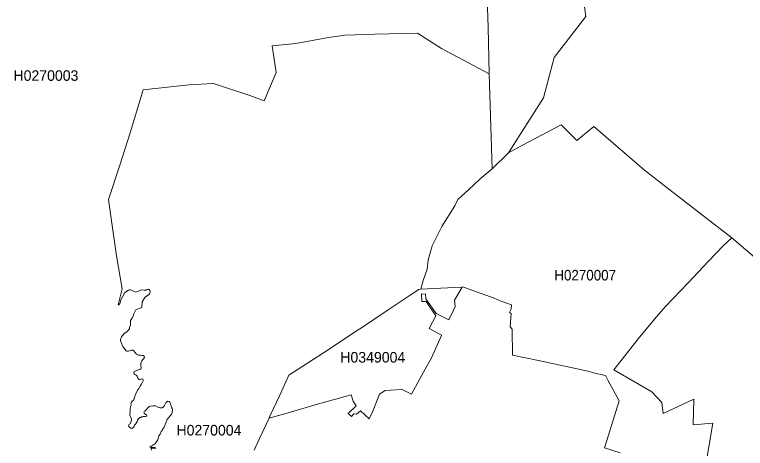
# Model space of a CAD drawing. Extents: x 369010 to 739155, y 6377141 to 6616555.
# Drawn here: x 407141 to 414085, y 6458637 to 6462758 of the extents above; entities that cross this region are included whole.
import ezdxf
from ezdxf.enums import TextEntityAlignment as Align

# ---------------------------------------------------------------- set-up
doc = ezdxf.new("R2010")
doc.units = 0
doc.header["$LTSCALE"] = 40
doc.layers.add('1', color=7, linetype='Continuous', lineweight=13)
doc.layers.add('2', color=7, linetype='Continuous')

msp = doc.modelspace()

# ---------------------------------------------------------------- linework, layer by layer
at = {"layer": '1'}
for points in [[(408412.9, 6460148.03), (408400.82, 6460147.7), (408391.72, 6460141.08), (408371.86, 6460141.08), (408355.8, 6460143.73), (408336.6, 6460138.59), (408302.84, 6460124.69), (408293.74, 6460122.54), (408275.86, 6460128.5), (408242.1, 6460142.4), (408233, 6460142.4), (408224.23, 6460139.75), (408187.49, 6460116.42), (408145.45, 6460036.98), (408145.78, 6460026.22), (408142.3, 6460013.14), (408132.54, 6460000.07), (408125.59, 6460001.56), (408162.33, 6460152.5), (408109.04, 6460466.62), (408067.16, 6460755.43), (408032.9, 6461001.7), (408141.31, 6461329.4), (408240.28, 6461636.41), (408362.09, 6462043.38), (408797.7, 6462090.05), (409029.9, 6462102.63), (409376.3, 6461990.09), (409513.34, 6461940.11), (409627.54, 6462207.89), (409587.48, 6462463.1), (409814.39, 6462482.79), (410124.54, 6462539.89), (410282.93, 6462563.06), (410562.8, 6462573.82), (410968.45, 6462580.61), (411198.83, 6462437.78), (411650.33, 6462196.8), (411641.39, 6462640.19), (411620.04, 6463290.95)], [(411620.04, 6463290.95), (411641.39, 6462640.19), (411650.33, 6462196.8), (411665.55, 6461694.99), (411678.79, 6461293.32), (411834.2, 6461446.57), (412167.53, 6461966.92), (412267.16, 6462351.38), (412568.05, 6462739.66), (412547.19, 6462906.48)], [(412547.19, 6462906.48), (412568.05, 6462739.66), (412267.16, 6462351.38), (412167.53, 6461966.92), (411834.2, 6461446.57), (411965.78, 6461518.73), (412333.19, 6461711.21), (412483.31, 6461561.93), (412644.18, 6461694), (413125.3, 6461280.41), (413369.75, 6461089.42), (413957.12, 6460637.26), (414215.97, 6460415.81)], [(409417.35, 6458619.6), (409468.98, 6458729.82), (409559.35, 6458924.79), (409567.46, 6458942), (409660.47, 6459141.1), (409748.02, 6459331.1), (409879.93, 6459418.16), (410075.55, 6459543.28), (410406.56, 6459763.4), (410436.85, 6459783.42), (410690.24, 6459951.91), (410890.83, 6460084.81), (410981.19, 6460145.21), (411001.05, 6460149.52), (411024.06, 6460231.11), (411060.3, 6460339.52), (411071.72, 6460427.07), (411109.79, 6460562.62), (411201.15, 6460744.67), (411324.78, 6460942.45), (411351.43, 6461003.19), (411454.2, 6461094.21), (411564.59, 6461197.65), (411678.79, 6461293.32), (411665.55, 6461694.99), (411650.33, 6462196.8), (411198.83, 6462437.78), (410968.45, 6462580.61), (410562.8, 6462573.82), (410282.93, 6462563.06), (410124.54, 6462539.89), (409814.39, 6462482.79), (409587.48, 6462463.1), (409627.54, 6462207.89), (409513.34, 6461940.11), (409376.3, 6461990.09), (409029.9, 6462102.63), (408797.7, 6462090.05), (408362.09, 6462043.38), (408240.28, 6461636.41), (408141.31, 6461329.4), (408032.9, 6461001.7), (408067.16, 6460755.43), (408109.04, 6460466.62), (408162.33, 6460152.5), (408125.59, 6460001.56), (408132.54, 6460000.07), (408142.3, 6460013.14), (408145.78, 6460026.22), (408145.45, 6460036.98), (408187.49, 6460116.42), (408224.23, 6460139.75), (408233, 6460142.4), (408242.1, 6460142.4), (408275.86, 6460128.5), (408293.74, 6460122.54), (408302.84, 6460124.69), (408336.6, 6460138.59), (408355.8, 6460143.73), (408371.86, 6460141.08), (408391.72, 6460141.08), (408400.82, 6460147.7), (408412.9, 6460148.03), (408426.14, 6460140.75), (408427.96, 6460123.2), (408421.34, 6460101.03), (408382.78, 6460073.72), (408354.31, 6460028.37), (408350.18, 6459975.57), (408292.58, 6459953.06), (408271.73, 6459909.7), (408270.24, 6459904.08), (408258.98, 6459872.63), (408247.4, 6459861.21), (408242.27, 6459851.28), (408240.78, 6459808.91), (408231.67, 6459786.57), (408231.84, 6459771.51), (408206.68, 6459744.7), (408181.86, 6459729.8), (408158.03, 6459697.69), (408146.27, 6459671.71), (408146.27, 6459658.47), (408158.19, 6459636.46), (408159.18, 6459627.85)], [(413701.25, 6458426.62), (413774.57, 6458875.63), (413589.7, 6458861.9), (413595.16, 6459103.7), (413302.72, 6458969.64), (413289.97, 6459072.42), (413196.13, 6459172.55), (412834.34, 6459382.24), (413077.8, 6459692.89), (413241.81, 6459887.86), (413323.9, 6459980.7), (413541.71, 6460208.77), (413735.18, 6460417.14), (413876.52, 6460564.27), (413957.12, 6460637.26), (413369.75, 6461089.42), (413125.3, 6461280.41), (412644.18, 6461694), (412483.31, 6461561.93), (412333.19, 6461711.21), (411965.78, 6461518.73), (411834.2, 6461446.57), (411678.79, 6461293.32), (411564.59, 6461197.65), (411454.2, 6461094.21), (411351.43, 6461003.19), (411324.78, 6460942.45), (411201.15, 6460744.67), (411109.79, 6460562.62), (411071.72, 6460427.07), (411060.3, 6460339.52), (411024.06, 6460231.11), (411001.05, 6460149.52), (411189.73, 6460160.61), (411392.97, 6460170.04), (411401.74, 6460170.37), (411484.66, 6460139.59), (411617.22, 6460093.08), (411697.66, 6460063.62), (411755.42, 6460040.12), (411861.84, 6460000.07), (411860.02, 6459958.53), (411843.97, 6459926.75), (411860.02, 6459917.15), (411850.92, 6459791.04), (411868.46, 6459770.84), (411872.6, 6459523.58), (412120.52, 6459470.46), (412603.46, 6459367.18), (412640.04, 6459354.44), (412755.06, 6459328.78), (412778.07, 6459285.75), (412884.99, 6459089.63), (412752.25, 6458660.97), (412745.63, 6458642.6), (412896.9, 6458593.95)], [(414215.97, 6460415.81), (413957.12, 6460637.26), (413876.52, 6460564.27), (413735.18, 6460417.14), (413541.71, 6460208.77), (413323.9, 6459980.7), (413241.81, 6459887.86), (413077.8, 6459692.89), (412834.34, 6459382.24), (413196.13, 6459172.55), (413289.97, 6459072.42), (413302.72, 6458969.64), (413595.16, 6459103.7), (413589.7, 6458861.9), (413774.57, 6458875.63), (413701.25, 6458426.62)], [(408270.9, 6458837.07), (408265.77, 6458830.45), (408260.47, 6458827.47), (408253.19, 6458825.98), (408244.25, 6458829.62), (408231.67, 6458837.73), (408226.54, 6458843.69), (408224.39, 6458851.14), (408225.05, 6458858.42), (408231.01, 6458865.87), (408237.63, 6458871), (408241.27, 6458875.47), (408248.72, 6458896.82), (408250.87, 6458905.59), (408250.21, 6458913.7), (408245.08, 6458928.76), (408236.14, 6458949.45), (408234.65, 6458961.2), (408239.12, 6458988.51), (408239.78, 6459015.82), (408242.27, 6459031.87), (408245.74, 6459038.16), (408247.23, 6459046.93), (408246.57, 6459059.51), (408248.06, 6459069.11), (408251.7, 6459076.56), (408258.32, 6459083.84), (408268.58, 6459092.77), (408272.39, 6459097.91), (408279.01, 6459118.59), (408296.72, 6459165.27), (408312.11, 6459194.06), (408320.22, 6459205.81), (408332.8, 6459229.32), (408342.4, 6459245.2), (408357.13, 6459266.55), (408362.42, 6459277.64), (408362.42, 6459287.9), (408360.93, 6459295.35), (408354.31, 6459298.17), (408350.51, 6459298.17), (408332.14, 6459288.57), (408324.69, 6459292.37), (408316.58, 6459299.65), (408308.47, 6459310.08), (408306.98, 6459315.87), (408304, 6459322.49), (408295.89, 6459332.09), (408283.48, 6459338.71), (408278.18, 6459344.67), (408275.37, 6459351.29), (408274.54, 6459359.4), (408278.18, 6459368.17), (408299.7, 6459378.1), (408332.14, 6459387.04), (408340.91, 6459392.83), (408344.71, 6459399.45), (408344.71, 6459407.56), (408341.74, 6459421.63), (408339.42, 6459437.85), (408339.42, 6459446.62), (408349.84, 6459468.8), (408363.25, 6459484.85), (408373.68, 6459501.07), (408373.18, 6459512), (408365.4, 6459519.11), (408348.85, 6459519.78), (408336.94, 6459523.42), (408318.9, 6459522.59), (408300.03, 6459530.37), (408267.26, 6459568.93), (408248.39, 6459571.25), (408222.74, 6459560.32), (408207.68, 6459559.33), (408199.57, 6459562.48), (408178.05, 6459593.09), (408168.29, 6459603.35), (408159.18, 6459627.85), (408158.19, 6459636.46), (408146.27, 6459658.47), (408146.27, 6459671.71), (408158.03, 6459697.69), (408181.86, 6459729.8), (408206.68, 6459744.7), (408231.84, 6459771.51), (408231.67, 6459786.57), (408240.78, 6459808.91), (408242.27, 6459851.28), (408247.4, 6459861.21), (408258.98, 6459872.63), (408270.24, 6459904.08), (408271.73, 6459909.7), (408292.58, 6459953.06), (408350.18, 6459975.57), (408354.31, 6460028.37), (408382.78, 6460073.72), (408421.34, 6460101.03), (408427.96, 6460123.2), (408426.14, 6460140.75), (408412.9, 6460148.03)], [(411392.97, 6460170.04), (411321.47, 6460044.59), (411328.59, 6459986.33), (411308.89, 6459944.13), (411268.51, 6459859.39), (411148.19, 6459918.97), (411049.21, 6460059.15), (411045.9, 6460103.01), (411007.51, 6460105), (411009.83, 6460032.18), (411051.2, 6460032.01), (411143.39, 6459894.64), (411079.5, 6459775.98), (411198.33, 6459712.09), (411197.34, 6459709.77), (411103, 6459497.43), (411025.22, 6459361.88), (410911.85, 6459153.18), (410824.13, 6459196.21), (410660.78, 6459185.79), (410609.8, 6459152.19), (410579.18, 6459077.55), (410542.44, 6458984.87), (410508.84, 6458918.83), (410427.25, 6458994.47), (410389.52, 6458961.86), (410363.86, 6458965.67), (410341.52, 6458940.84), (410310.9, 6458966.66), (410386.54, 6459040.14), (410358.24, 6459084.67), (410339.53, 6459146.73), (409997.6, 6459050.9), (409707.47, 6458966.16), (409568.12, 6458927.11), (409559.35, 6458924.79), (409468.98, 6458729.82), (409417.35, 6458619.6)], [(412896.9, 6458593.95), (412745.63, 6458642.6), (412752.25, 6458660.97), (412884.99, 6459089.63), (412778.07, 6459285.75), (412755.06, 6459328.78), (412640.04, 6459354.44), (412603.46, 6459367.18), (412120.52, 6459470.46), (411872.6, 6459523.58), (411868.46, 6459770.84), (411850.92, 6459791.04), (411860.02, 6459917.15), (411843.97, 6459926.75), (411860.02, 6459958.53), (411861.84, 6460000.07), (411755.42, 6460040.12), (411697.66, 6460063.62), (411617.22, 6460093.08), (411484.66, 6460139.59), (411401.74, 6460170.37), (411392.97, 6460170.04)], [(408159.18, 6459627.85), (408168.29, 6459603.35), (408178.05, 6459593.09), (408199.57, 6459562.48), (408207.68, 6459559.33), (408222.74, 6459560.32), (408248.39, 6459571.25), (408267.26, 6459568.93), (408300.03, 6459530.37), (408318.9, 6459522.59), (408336.94, 6459523.42), (408348.85, 6459519.78), (408365.4, 6459519.11), (408373.18, 6459512), (408373.68, 6459501.07), (408363.25, 6459484.85), (408349.84, 6459468.8), (408339.42, 6459446.62), (408339.42, 6459437.85), (408341.74, 6459421.63), (408344.71, 6459407.56), (408344.71, 6459399.45), (408340.91, 6459392.83), (408332.14, 6459387.04), (408299.7, 6459378.1), (408278.18, 6459368.17), (408274.54, 6459359.4), (408275.37, 6459351.29), (408278.18, 6459344.67), (408283.48, 6459338.71), (408295.89, 6459332.09), (408304, 6459322.49), (408306.98, 6459315.87), (408308.47, 6459310.08), (408316.58, 6459299.65), (408324.69, 6459292.37), (408332.14, 6459288.57), (408350.51, 6459298.17), (408354.31, 6459298.17), (408360.93, 6459295.35)], [(408360.93, 6459295.35), (408362.42, 6459287.9), (408362.42, 6459277.64), (408357.13, 6459266.55), (408342.4, 6459245.2), (408332.8, 6459229.32), (408320.22, 6459205.81), (408312.11, 6459194.06), (408296.72, 6459165.27), (408279.01, 6459118.59), (408272.39, 6459097.91), (408268.58, 6459092.77), (408258.32, 6459083.84), (408251.7, 6459076.56), (408248.06, 6459069.11), (408246.57, 6459059.51), (408247.23, 6459046.93), (408245.74, 6459038.16), (408242.27, 6459031.87), (408239.78, 6459015.82), (408239.12, 6458988.51), (408234.65, 6458961.2), (408236.14, 6458949.45), (408245.08, 6458928.76), (408250.21, 6458913.7), (408250.87, 6458905.59), (408248.72, 6458896.82), (408241.27, 6458875.47), (408237.63, 6458871), (408231.01, 6458865.87), (408225.05, 6458858.42), (408224.39, 6458851.14), (408226.54, 6458843.69), (408231.67, 6458837.73), (408244.25, 6458829.62), (408253.19, 6458825.98), (408260.47, 6458827.47), (408265.77, 6458830.45), (408270.9, 6458837.07), (408276.03, 6458846.67), (408279.67, 6458856.27), (408288.61, 6458868.02), (408295.23, 6458875.47), (408305.49, 6458890.86), (408309.3, 6458905.59), (408315.92, 6458914.53), (408330.65, 6458929.26), (408340.91, 6458931.41), (408346.2, 6458935.05), (408354.98, 6458935.88), (408363.91, 6458939.52), (408373.51, 6458941.01), (408379.3, 6458940.35), (408385.92, 6458936.54), (408392.54, 6458939.52), (408397.01, 6458943.99), (408397.01, 6458947.63), (408393.37, 6458955.08), (408378.64, 6458964.67), (408373.51, 6458970.47), (408370.53, 6458975.6), (408369.04, 6458981.56), (408373.51, 6458987.51), (408378.64, 6458991.82), (408385.92, 6458996.29), (408394.03, 6459005.89), (408402.97, 6459018.46), (408412.57, 6459029.55), (408418.53, 6459033.86), (408430.28, 6459037.5), (408453.95, 6459040.48), (408466.36, 6459039.81), (408480.43, 6459040.48), (408501.78, 6459027.24), (408509.89, 6459023.59), (408524.29, 6459021.44), (408532.4, 6459021.44), (408542.66, 6459022.77), (408550.1, 6459025.08), (408556.06, 6459030.88), (408564.17, 6459043.45), (408577.41, 6459068.61), (408586.35, 6459079.53), (408595.12, 6459086.15), (408609.19, 6459083.34), (408616.47, 6459074.4), (408622.43, 6459064.14), (408628.39, 6459037.5), (408632.03, 6459026.57), (408637.16, 6459015.48), (408640.8, 6459005.22), (408640.47, 6458999.6), (408639.31, 6458978.58), (408630.54, 6458962.85), (408591.98, 6458909.89), (408584.03, 6458895.66), (408561.36, 6458838.89), (408556.39, 6458829.95), (408550.44, 6458824.49), (408548.45, 6458816.05)], [(408482.08, 6458636.48), (408480.43, 6458639.96), (408473.15, 6458644.26), (408436.57, 6458646.41), (408427.47, 6458646.91), (408428.46, 6458649.89), (408434.91, 6458655.68), (408473.97, 6458678.52), (408489.7, 6458698.21), (408501.12, 6458717.58), (408506.58, 6458733.3), (408507.57, 6458747.37), (408511.54, 6458754.82), (408523.79, 6458770.21), (408534.71, 6458795.86), (408540.67, 6458803.31), (408548.45, 6458816.05), (408550.44, 6458824.49), (408556.39, 6458829.95), (408561.36, 6458838.89), (408584.03, 6458895.66), (408591.98, 6458909.89), (408630.54, 6458962.85), (408639.31, 6458978.58), (408640.47, 6458999.6), (408640.8, 6459005.22), (408637.16, 6459015.48), (408632.03, 6459026.57), (408628.39, 6459037.5), (408622.43, 6459064.14), (408616.47, 6459074.4), (408609.19, 6459083.34), (408595.12, 6459086.15), (408586.35, 6459079.53), (408577.41, 6459068.61), (408564.17, 6459043.45), (408556.06, 6459030.88), (408550.1, 6459025.08), (408542.66, 6459022.77), (408532.4, 6459021.44), (408524.29, 6459021.44), (408509.89, 6459023.59), (408501.78, 6459027.24), (408480.43, 6459040.48), (408466.36, 6459039.81), (408453.95, 6459040.48), (408430.28, 6459037.5), (408418.53, 6459033.86), (408412.57, 6459029.55), (408402.97, 6459018.46), (408394.03, 6459005.89), (408385.92, 6458996.29), (408378.64, 6458991.82), (408373.51, 6458987.51), (408369.04, 6458981.56), (408370.53, 6458975.6), (408373.51, 6458970.47), (408378.64, 6458964.67), (408393.37, 6458955.08), (408397.01, 6458947.63), (408397.01, 6458943.99), (408392.54, 6458939.52), (408385.92, 6458936.54), (408379.3, 6458940.35), (408373.51, 6458941.01), (408363.91, 6458939.52), (408354.98, 6458935.88), (408346.2, 6458935.05), (408340.91, 6458931.41), (408330.65, 6458929.26), (408315.92, 6458914.53), (408309.3, 6458905.59), (408305.49, 6458890.86), (408295.23, 6458875.47), (408288.61, 6458868.02), (408279.67, 6458856.27), (408276.03, 6458846.67), (408270.9, 6458837.07)], [(408548.45, 6458816.05), (408540.67, 6458803.31), (408534.71, 6458795.86), (408523.79, 6458770.21), (408511.54, 6458754.82), (408507.57, 6458747.37), (408506.58, 6458733.3), (408501.12, 6458717.58), (408489.7, 6458698.21), (408473.97, 6458678.52), (408434.91, 6458655.68), (408428.46, 6458649.89), (408427.47, 6458646.91), (408436.57, 6458646.41), (408473.15, 6458644.26), (408480.43, 6458639.96), (408482.08, 6458636.48)], [(408471.82, 6458634.33), (408461.39, 6458639.79), (408438.06, 6458638.96), (408441.7, 6458620.43)], [(408441.7, 6458620.43), (408438.06, 6458638.96), (408461.39, 6458639.79), (408471.82, 6458634.33)]]:
    msp.add_lwpolyline(points, dxfattribs=at)
msp.add_lwpolyline([(411392.97, 6460170.04), (411189.73, 6460160.61), (411001.05, 6460149.52), (410981.19, 6460145.21), (410890.83, 6460084.81), (410690.24, 6459951.91), (410436.85, 6459783.42), (410406.56, 6459763.4), (410075.55, 6459543.28), (409879.93, 6459418.16), (409748.02, 6459331.1), (409660.47, 6459141.1), (409567.46, 6458942), (409559.35, 6458924.79), (409568.12, 6458927.11), (409707.47, 6458966.16), (409997.6, 6459050.9), (410339.53, 6459146.73), (410358.24, 6459084.67), (410386.54, 6459040.14), (410310.9, 6458966.66), (410341.52, 6458940.84), (410363.86, 6458965.67), (410389.52, 6458961.86), (410427.25, 6458994.47), (410508.84, 6458918.83), (410542.44, 6458984.87), (410579.18, 6459077.55), (410609.8, 6459152.19), (410660.78, 6459185.79), (410824.13, 6459196.21), (410911.85, 6459153.18), (411025.22, 6459361.88), (411103, 6459497.43), (411197.34, 6459709.77), (411198.33, 6459712.09), (411079.5, 6459775.98), (411143.39, 6459894.64), (411051.2, 6460032.01), (411009.83, 6460032.18), (411007.51, 6460105), (411045.9, 6460103.01), (411049.21, 6460059.15), (411148.19, 6459918.97), (411268.51, 6459859.39), (411308.89, 6459944.13), (411328.59, 6459986.33), (411321.47, 6460044.59)], close=True, dxfattribs=at)

# ---------------------------------------------------------------- texts
at = {"layer": '2'}
for s, p in [('H0270003', (407438.58, 6462129.37)), ('H0349004', (410544.45, 6459452.19)), ('H0270004', (408987.71, 6458759.4))]:
    msp.add_text(s, height=100, dxfattribs=at).set_placement(p, align=Align.CENTER)
at = {"layer": '2', "width": 0.95}
msp.add_text('H0270007', height=100, dxfattribs=at).set_placement((412562.79, 6460232.49), align=Align.CENTER)

doc.saveas('drawing.dxf')
